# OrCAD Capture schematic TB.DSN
size Custom
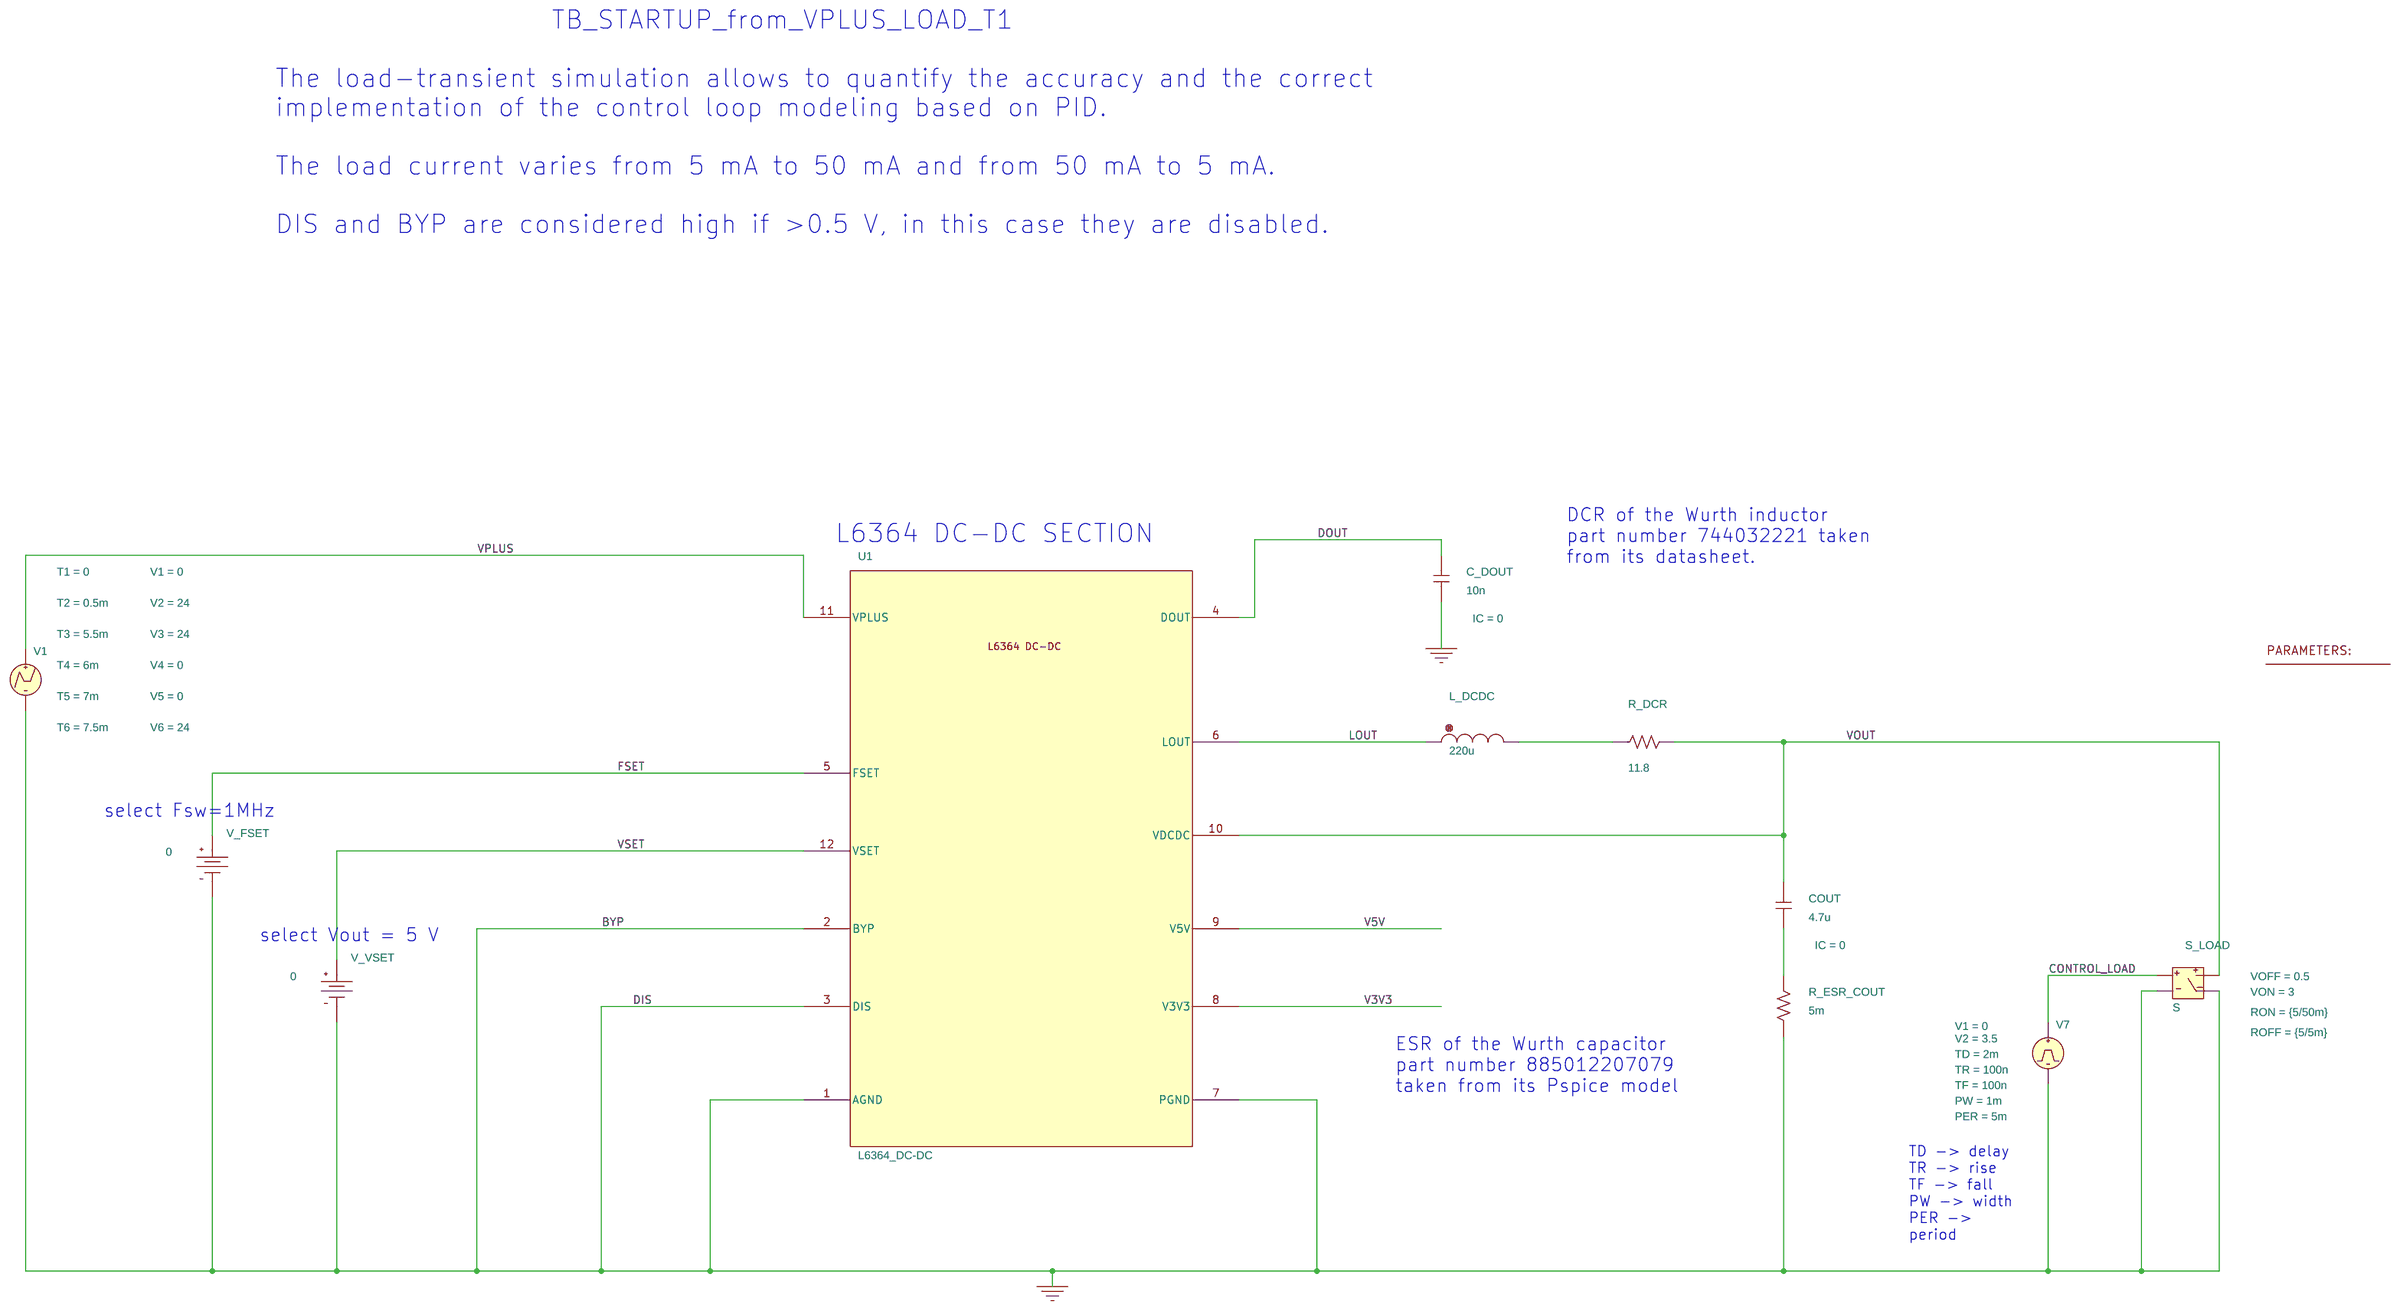
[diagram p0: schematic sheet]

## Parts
1  PARAM
C_DOUT  10n  [RAD/CK05]
COUT  4.7u  [RAD/CK05]
L_DCDC  220u  [DISC/.350x.175/LS.200x.100/.034]
R_DCR  11.8  [AX/RC05]
R_ESR_COUT  5m  [AX/RC05]
S_LOAD  S
U1  L6364_DC-DC
V1  VPWL
V7  VPULSE
V_FSET  VDC
V_VSET  VDC

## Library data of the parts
1 = PARAM: Iout: 50mA; Vout: 5V
C_DOUT COUT = C: IC: 0
L_DCDC = L
R_DCR R_ESR_COUT = R
S_LOAD = S: ROFF: {5/5m}; RON: {5/50m}; VOFF: 0.5; VON: 3
U1 = L6364_DC-DC
V1 = VPWL: T1: 0; T2: 0.5m; T3: 5.5m; T4: 6m; T5: 7m; T6: 7.5m; V1: 0; V2: 24; V3: 24; V4: 0; V5: 0; V6: 24
V7 = VPULSE: PER: 5m; PW: 1m; TD: 2m; TF: 100n; TR: 100n; V1: 0; V2: 3.5
V_FSET V_VSET = VDC: DC: 0

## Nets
V3V3: U1.8(V3V3)
V5V: U1.9(V5V)
0: C_DOUT.1 R_ESR_COUT.1 S_LOAD.1(2) S_LOAD.3(4) U1.1(AGND) U1.2(BYP) U1.3(DIS) U1.7(PGND) V1.2(-) V7.2(-) V_FSET.1(-) V_VSET.1(-)
CONTROL_LOAD: S_LOAD.0(1) V7.1(+)
DOUT: C_DOUT.2 U1.4(DOUT)
FSET: U1.5(FSET) V_FSET.0(+)
LOUT: L_DCDC.1 U1.6(LOUT)
VOUT: COUT.2 R_DCR.2 S_LOAD.2(3) U1.10(VDCDC)
VPLUS: U1.11(VPLUS) V1.1(+)
VSET: U1.12(VSET) V_VSET.0(+)
N8450096: L_DCDC.2 R_DCR.1
N8450204: COUT.1 R_ESR_COUT.2

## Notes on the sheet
- TB_STARTUP_from_VPLUS_LOAD_T1
  The load-transient simulation allows to quantify the accuracy and the correct
  implementation of the control loop modeling based on PID.
  The load current varies from 5 mA to 50 mA and from 50 mA to 5 mA.
  DIS and BYP are considered high if >0.5 V, in this case they are disabled.
- DCR of the Wurth inductor
  part number 744032221 taken
  from its datasheet.
- L6364 DC-DC SECTION
- select Fsw=1MHz
- select Vout = 5 V
- ESR of the Wurth capacitor
  part number 885012207079
  taken from its Pspice model
- TD -> delay
  TR -> rise
  TF -> fall
  PW -> width
  PER ->
  period
